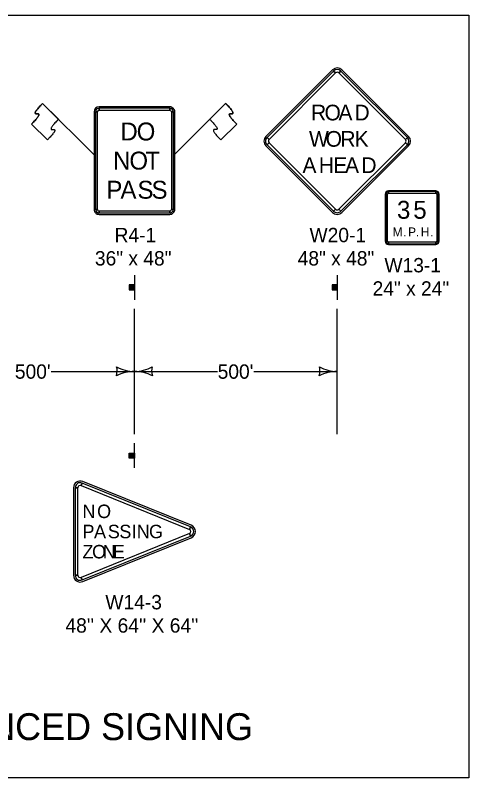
# Model space of a CAD drawing. Extents: x -2134934 to -2119606, y -2139046 to -2137036.
# Drawn here: x -2120111 to -2119606, y -2137987 to -2137136 of the extents above; entities that cross this region are included whole.
import ezdxf

# ---------------------------------------------------------------- set-up
doc = ezdxf.new("R2010")
doc.units = 0
for name, color, linetype in [('dsnStdLabel', 7, 'Continuous'), ('Level 2', 7, 'Continuous'), ('Level 5', 7, 'Continuous')]:
    doc.layers.add(name, color=color, linetype=linetype)

msp = doc.modelspace()

# ---------------------------------------------------------------- linework, layer by layer
at = {"layer": 'dsnStdLabel'}
for p, q in [((-2119757.65, -2137196.82), (-2119831.9, -2137271.07)), ((-2119756.32, -2137198.15), (-2119754.11, -2137200.36)), ((-2119750.58, -2137200.36), (-2119748.37, -2137198.15)), ((-2119672.8, -2137271.07), (-2119747.04, -2137196.82)), ((-2120023.38, -2137291.63), (-2120080.72, -2137234.33)), ((-2120080.72, -2137234.33), (-2120063.03, -2137252.01)), ((-2119934.09, -2137291.63), (-2119876.77, -2137234.32)), ((-2119876.77, -2137234.32), (-2119894.45, -2137252)), ((-2120023.38, -2137243.74), (-2120023.38, -2137352.49)), ((-2120021.82, -2137243.74), (-2120019.63, -2137243.74)), ((-2119939.01, -2137238.12), (-2120017.76, -2137238.12)), ((-2120017.76, -2137241.87), (-2120017.76, -2137239.68)), ((-2119939.01, -2137239.68), (-2119939.01, -2137241.87)), ((-2119937.13, -2137243.74), (-2119934.94, -2137243.74)), ((-2119933.38, -2137352.49), (-2119933.38, -2137243.74)), ((-2120075.41, -2137275), (-2120093.09, -2137257.33)), ((-2119882.07, -2137274.99), (-2119864.39, -2137257.31)), ((-2119828.36, -2137274.6), (-2119830.57, -2137272.39)), ((-2119830.57, -2137280.35), (-2119828.36, -2137278.14)), ((-2119674.12, -2137272.39), (-2119676.33, -2137274.6)), ((-2119676.33, -2137278.14), (-2119674.12, -2137280.35)), ((-2119831.9, -2137281.67), (-2119757.65, -2137355.92)), ((-2119747.04, -2137355.92), (-2119672.8, -2137281.67)), ((-2119698.83, -2137335.51), (-2119698.83, -2137388.01)), ((-2119697.89, -2137335.51), (-2119696.33, -2137335.51)), ((-2119642.58, -2137331.76), (-2119695.08, -2137331.76)), ((-2119695.08, -2137334.26), (-2119695.08, -2137332.7)), ((-2119642.58, -2137332.7), (-2119642.58, -2137334.26)), ((-2119641.33, -2137335.51), (-2119639.76, -2137335.51)), ((-2119638.83, -2137388.01), (-2119638.83, -2137335.51)), ((-2120019.63, -2137352.49), (-2120021.82, -2137352.49)), ((-2120017.76, -2137356.55), (-2120017.76, -2137354.37)), ((-2119939.01, -2137354.37), (-2119939.01, -2137356.55)), ((-2119934.94, -2137352.49), (-2119937.13, -2137352.49)), ((-2119754.11, -2137352.38), (-2119756.32, -2137354.59)), ((-2119748.37, -2137354.59), (-2119750.58, -2137352.38)), ((-2120017.76, -2137358.12), (-2119939.01, -2137358.12)), ((-2119696.33, -2137388.01), (-2119697.89, -2137388.01)), ((-2119639.76, -2137388.01), (-2119641.33, -2137388.01)), ((-2119695.08, -2137390.82), (-2119695.08, -2137389.26)), ((-2119695.08, -2137391.76), (-2119642.58, -2137391.76)), ((-2119642.58, -2137389.26), (-2119642.58, -2137390.82)), ((-2120037.86, -2137660.69), (-2120036.68, -2137657.79)), ((-2119915.16, -2137704.93), (-2120035.98, -2137656.05)), ((-2120046.29, -2137663.01), (-2120046.29, -2137760.76)), ((-2120044.42, -2137663.01), (-2120041.29, -2137663.01)), ((-2119915.86, -2137706.67), (-2119917.03, -2137709.57)), ((-2120035.98, -2137767.71), (-2119915.16, -2137718.84)), ((-2119917.03, -2137714.2), (-2119915.86, -2137717.1)), ((-2120041.29, -2137760.76), (-2120044.42, -2137760.76)), ((-2120036.68, -2137765.97), (-2120037.86, -2137763.08))]:
    msp.add_line(p, q, dxfattribs=at)
for points in [[(-2120726.97, -2137135.95), (-2119605.73, -2137135.95), (-2119605.73, -2137986.59), (-2120726.97, -2137986.59)], [(-2119756.32, -2137198.15), (-2119830.57, -2137272.39), (-2119828.36, -2137274.6), (-2119754.11, -2137200.36), (-2119756.32, -2137198.15)], [(-2119674.12, -2137272.39), (-2119748.37, -2137198.15), (-2119750.58, -2137200.36), (-2119676.33, -2137274.6), (-2119674.12, -2137272.39)], [(-2120021.82, -2137243.74), (-2120021.82, -2137352.49), (-2120019.63, -2137352.49), (-2120019.63, -2137243.74), (-2120021.82, -2137243.74)], [(-2119939.01, -2137239.68), (-2120017.76, -2137239.68), (-2120017.76, -2137241.87), (-2119939.01, -2137241.87), (-2119939.01, -2137239.68)], [(-2119934.94, -2137352.49), (-2119934.94, -2137243.74), (-2119937.13, -2137243.74), (-2119937.13, -2137352.49), (-2119934.94, -2137352.49)], [(-2119830.57, -2137280.35), (-2119756.32, -2137354.59), (-2119754.11, -2137352.38), (-2119828.36, -2137278.14), (-2119830.57, -2137280.35)], [(-2119748.37, -2137354.59), (-2119674.12, -2137280.35), (-2119676.33, -2137278.14), (-2119750.58, -2137352.38), (-2119748.37, -2137354.59)], [(-2119697.89, -2137335.51), (-2119697.89, -2137388.01), (-2119696.33, -2137388.01), (-2119696.33, -2137335.51), (-2119697.89, -2137335.51)], [(-2119642.58, -2137332.7), (-2119695.08, -2137332.7), (-2119695.08, -2137334.26), (-2119642.58, -2137334.26), (-2119642.58, -2137332.7)], [(-2119639.76, -2137388.01), (-2119639.76, -2137335.51), (-2119641.33, -2137335.51), (-2119641.33, -2137388.01), (-2119639.76, -2137388.01)], [(-2120017.76, -2137356.55), (-2119939.01, -2137356.55), (-2119939.01, -2137354.37), (-2120017.76, -2137354.37), (-2120017.76, -2137356.55)], [(-2119695.08, -2137390.82), (-2119642.58, -2137390.82), (-2119642.58, -2137389.26), (-2119695.08, -2137389.26), (-2119695.08, -2137390.82)], [(-2119915.86, -2137706.67), (-2120036.68, -2137657.79), (-2120037.86, -2137660.69), (-2119917.03, -2137709.57), (-2119915.86, -2137706.67)], [(-2120044.42, -2137663.01), (-2120044.42, -2137760.76), (-2120041.29, -2137760.76), (-2120041.29, -2137663.01), (-2120044.42, -2137663.01)], [(-2120036.68, -2137765.97), (-2119915.86, -2137717.1), (-2119917.03, -2137714.2), (-2120037.86, -2137763.08), (-2120036.68, -2137765.97)]]:
    msp.add_lwpolyline(points, close=True, dxfattribs=at)
for centre, radius, start, end in [((-2119752.35, -2137202.12), 7.5, 44.99999, 134.99974), ((-2119752.35, -2137202.12), 5.62, 44.99999, 134.99974), ((-2119752.35, -2137202.12), 2.5, 44.99999, 134.99974), ((-2120017.76, -2137243.74), 5.62, 90.00021, 179.99985), ((-2120017.76, -2137243.74), 4.06, 90.00021, 179.99985), ((-2120017.76, -2137243.74), 1.87, 90.00021, 179.99985), ((-2119939.01, -2137243.74), 5.62, 0, 90.00021), ((-2119939.01, -2137243.74), 4.06, 0, 90.00021), ((-2119939.01, -2137243.74), 1.87, 0, 90.00021), ((-2119826.59, -2137276.37), 7.5, 134.99974, 224.99995), ((-2119826.59, -2137276.37), 5.62, 134.99974, 224.99995), ((-2119826.59, -2137276.37), 2.5, 134.99974, 224.99995), ((-2119678.1, -2137276.37), 2.5, 315.00016, 44.9998), ((-2119678.1, -2137276.37), 5.62, 315.00016, 44.9998), ((-2119678.1, -2137276.37), 7.5, 315.00016, 44.9998), ((-2119695.08, -2137335.51), 3.75, 90.00021, 179.99985), ((-2119695.08, -2137335.51), 2.81, 90.00021, 179.99985), ((-2119695.08, -2137335.51), 1.25, 90.00021, 179.99985), ((-2119642.58, -2137335.51), 3.75, 0, 90.00021), ((-2119642.58, -2137335.51), 2.81, 0, 90.00021), ((-2119642.58, -2137335.51), 1.25, 0, 90.00021), ((-2120017.76, -2137352.49), 5.62, 179.99985, 270.00006), ((-2120017.76, -2137352.49), 4.06, 179.99985, 270.00006), ((-2120017.76, -2137352.49), 1.87, 179.99985, 270.00006), ((-2119939.01, -2137352.49), 5.62, 270.00006, 0.00027), ((-2119939.01, -2137352.49), 4.06, 270.00006, 0.00027), ((-2119939.01, -2137352.49), 1.87, 270.00006, 0.00027), ((-2119752.35, -2137350.62), 5.62, 224.99995, 315.00016), ((-2119752.35, -2137350.62), 2.5, 224.99995, 315.00016), ((-2119752.35, -2137350.62), 7.5, 224.99995, 315.00016), ((-2119695.08, -2137388.01), 3.75, 179.99985, 270.00006), ((-2119695.08, -2137388.01), 2.81, 179.99985, 270.00006), ((-2119695.08, -2137388.01), 1.25, 179.99985, 270.00006), ((-2119642.58, -2137388.01), 3.75, 270.00006, 0.00027), ((-2119642.58, -2137388.01), 2.81, 270.00006, 0.00027), ((-2119642.58, -2137388.01), 1.25, 270.00006, 0.00027), ((-2120038.79, -2137663.01), 7.5, 67.97571, 179.99985), ((-2120038.79, -2137663.01), 5.62, 67.97571, 179.99985), ((-2120038.79, -2137663.01), 2.5, 67.97571, 179.99985), ((-2119917.97, -2137711.88), 2.5, 292.02456, 67.97541), ((-2119917.97, -2137711.88), 5.62, 292.02456, 67.97541), ((-2119917.97, -2137711.88), 7.5, 292.02456, 67.97598), ((-2120038.79, -2137760.76), 7.5, 179.99985, 292.02456), ((-2120038.79, -2137760.76), 5.62, 179.99985, 292.02456), ((-2120038.79, -2137760.76), 2.5, 179.99985, 292.02456)]:
    msp.add_arc(centre, radius, start, end, dxfattribs=at)
for points in [[(-2120093.09, -2137257.33), (-2120080.71, -2137244.95), (-2120093.09, -2137246.72), (-2120080.72, -2137234.33)], [(-2119864.39, -2137257.31), (-2119876.77, -2137244.93), (-2119864.39, -2137246.7), (-2119876.77, -2137234.32)], [(-2120063.03, -2137252.01), (-2120075.4, -2137264.4), (-2120063.03, -2137262.62), (-2120075.41, -2137275)], [(-2119894.45, -2137252), (-2119882.07, -2137264.38), (-2119894.44, -2137262.61), (-2119882.07, -2137274.99)]]:
    msp.add_open_spline(points, degree=2, dxfattribs=at)
at = {"layer": 'Level 2'}
for p, q in [((-2119978.38, -2137425.94), (-2119978.38, -2137453.44)), ((-2119752.35, -2137425.94), (-2119752.35, -2137453.44)), ((-2119983.71, -2137436.8), (-2119983.71, -2137442.39)), ((-2119983.39, -2137442.39), (-2119983.39, -2137436.8)), ((-2119983.16, -2137436.8), (-2119983.16, -2137442.39)), ((-2119982.85, -2137442.39), (-2119982.85, -2137436.8)), ((-2119982.62, -2137436.8), (-2119982.64, -2137442.39)), ((-2119982.21, -2137442.39), (-2119982.19, -2137436.8)), ((-2119981.98, -2137436.8), (-2119981.98, -2137442.39)), ((-2119981.55, -2137442.39), (-2119981.55, -2137436.8)), ((-2119981.18, -2137436.8), (-2119981.18, -2137442.39)), ((-2119980.86, -2137442.39), (-2119980.84, -2137436.8)), ((-2119980.63, -2137436.8), (-2119980.63, -2137442.39)), ((-2119980.37, -2137442.39), (-2119980.37, -2137436.8)), ((-2119980.03, -2137436.8), (-2119980.03, -2137442.39)), ((-2119979.83, -2137442.39), (-2119979.83, -2137436.8)), ((-2119979.6, -2137436.8), (-2119979.6, -2137442.39)), ((-2119979.34, -2137442.39), (-2119979.34, -2137436.8)), ((-2119979.08, -2137436.8), (-2119979.08, -2137442.39)), ((-2119978.79, -2137442.39), (-2119978.79, -2137436.8)), ((-2119757.67, -2137436.8), (-2119757.67, -2137442.39)), ((-2119757.35, -2137442.39), (-2119757.35, -2137436.8)), ((-2119757.13, -2137436.8), (-2119757.13, -2137442.39)), ((-2119756.81, -2137442.39), (-2119756.81, -2137436.8)), ((-2119756.58, -2137436.8), (-2119756.6, -2137442.39)), ((-2119756.17, -2137442.39), (-2119756.15, -2137436.8)), ((-2119755.95, -2137436.8), (-2119755.95, -2137442.39)), ((-2119755.52, -2137442.39), (-2119755.52, -2137436.8)), ((-2119755.14, -2137436.8), (-2119755.14, -2137442.39)), ((-2119754.82, -2137442.39), (-2119754.8, -2137436.8)), ((-2119754.6, -2137436.8), (-2119754.6, -2137442.39)), ((-2119754.33, -2137442.39), (-2119754.33, -2137436.8)), ((-2119754, -2137436.8), (-2119754, -2137442.39)), ((-2119753.79, -2137442.39), (-2119753.79, -2137436.8)), ((-2119753.57, -2137436.8), (-2119753.57, -2137442.39)), ((-2119753.3, -2137442.39), (-2119753.3, -2137436.8)), ((-2119753.04, -2137436.8), (-2119753.04, -2137442.39)), ((-2119752.76, -2137442.39), (-2119752.76, -2137436.8)), ((-2119978.38, -2137603.44), (-2119978.38, -2137463.44)), ((-2119752.35, -2137603.44), (-2119752.35, -2137463.44)), ((-2120071.15, -2137533.44), (-2119978.38, -2137533.44)), ((-2119978.38, -2137533.44), (-2119885.61, -2137533.44)), ((-2119845.11, -2137533.44), (-2119752.35, -2137533.44)), ((-2119978.38, -2137640.94), (-2119978.38, -2137613.44)), ((-2119983.71, -2137630.08), (-2119983.71, -2137624.49)), ((-2119983.39, -2137624.49), (-2119983.39, -2137630.08)), ((-2119983.16, -2137630.08), (-2119983.16, -2137624.49)), ((-2119982.85, -2137624.49), (-2119982.85, -2137630.08)), ((-2119982.62, -2137630.08), (-2119982.64, -2137624.49)), ((-2119982.21, -2137624.49), (-2119982.19, -2137630.08)), ((-2119981.98, -2137630.08), (-2119981.98, -2137624.49)), ((-2119981.55, -2137624.49), (-2119981.55, -2137630.08)), ((-2119981.18, -2137630.08), (-2119981.18, -2137624.49)), ((-2119980.86, -2137624.49), (-2119980.84, -2137630.08)), ((-2119980.63, -2137630.08), (-2119980.63, -2137624.49)), ((-2119980.37, -2137624.49), (-2119980.37, -2137630.08)), ((-2119980.03, -2137630.08), (-2119980.03, -2137624.49)), ((-2119979.83, -2137624.49), (-2119979.83, -2137630.08)), ((-2119979.6, -2137630.08), (-2119979.6, -2137624.49)), ((-2119979.34, -2137624.49), (-2119979.34, -2137630.08)), ((-2119979.08, -2137630.08), (-2119979.08, -2137624.49)), ((-2119978.79, -2137624.49), (-2119978.79, -2137630.08))]:
    msp.add_line(p, q, dxfattribs=at)
for points in [[(-2119978.48, -2137442.39), (-2119978.48, -2137436.76), (-2119984.1, -2137436.76), (-2119984.1, -2137442.39)], [(-2119752.44, -2137442.39), (-2119752.44, -2137436.76), (-2119758.07, -2137436.76), (-2119758.07, -2137442.39)], [(-2119978.48, -2137624.49), (-2119978.48, -2137630.12), (-2119984.1, -2137630.12), (-2119984.1, -2137624.49)]]:
    msp.add_lwpolyline(points, close=True, dxfattribs=at)
for centre, radius, start, end in [((-2120014, -2137532.82), 16.42, 341.26665, 16.73335), ((-2119979.11, -2137575.93), 42.5, 89.0176, 117.07249), ((-2119977.63, -2137490.95), 42.5, 240.92751, 268.9824), ((-2119979.14, -2137490.95), 42.5, 271.0176, 299.07249), ((-2119977.65, -2137575.93), 42.5, 62.92751, 90.9824), ((-2119942.76, -2137532.82), 16.42, 163.26665, 198.73335), ((-2119787.96, -2137532.82), 16.42, 341.26665, 16.73335), ((-2119753.07, -2137575.93), 42.5, 89.0176, 117.07249), ((-2119751.59, -2137490.95), 42.5, 240.92751, 268.9824)]:
    msp.add_arc(centre, radius, start, end, dxfattribs=at)
at = {"layer": 'Level 5'}
for p, q in [((-2120093.09, -2137257.33), (-2120075.41, -2137275)), ((-2119864.39, -2137257.31), (-2119882.07, -2137274.99))]:
    msp.add_line(p, q, dxfattribs=at)
for points in [[(-2120080.72, -2137234.33), (-2120093.09, -2137246.72), (-2120080.71, -2137244.95), (-2120093.09, -2137257.33)], [(-2119876.77, -2137234.32), (-2119864.39, -2137246.7), (-2119876.77, -2137244.93), (-2119864.39, -2137257.31)], [(-2120063.03, -2137252.01), (-2120075.4, -2137264.4), (-2120063.03, -2137262.62), (-2120075.41, -2137275)], [(-2119894.45, -2137252), (-2119882.07, -2137264.38), (-2119894.44, -2137262.61), (-2119882.07, -2137274.99)]]:
    msp.add_open_spline(points, degree=2, dxfattribs=at)

# ---------------------------------------------------------------- texts
at = {"layer": 'dsnStdLabel'}
for s, height, p in [('R', 17.5, (-2119781.51, -2137253.25)), ('O', 17.5, (-2119766.5, -2137253.25)), ('A', 17.5, (-2119750.95, -2137253.25)), ('D', 17.5, (-2119733.07, -2137253.25)), ('D', 20, (-2119994.01, -2137275.62)), ('O', 20, (-2119975.88, -2137275.62)), ('W', 17.5, (-2119783.79, -2137282.62)), ('O', 17.5, (-2119765.2, -2137282.62)), ('R', 17.5, (-2119748.79, -2137282.62)), ('K', 17.5, (-2119732.93, -2137282.62)), ('N', 20, (-2120002.13, -2137308.12)), ('O', 20, (-2119984.01, -2137308.12)), ('T', 20, (-2119966.19, -2137308.12)), ('A', 17.5, (-2119791.07, -2137312)), ('H', 17.5, (-2119772.86, -2137312)), ('E', 17.5, (-2119756.63, -2137312)), ('A', 17.5, (-2119743.59, -2137312)), ('D', 17.5, (-2119725.38, -2137312)), ('P', 20, (-2120009.65, -2137340.62)), ('A', 20, (-2119993.96, -2137340.62)), ('S', 20, (-2119974.99, -2137340.62)), ('S', 20, (-2119959.3, -2137340.62)), ('3', 20, (-2119685.68, -2137363)), ('5', 20, (-2119667.55, -2137363)), ('R4-1', 16, (-2120000.55, -2137389.12)), ('W20-1', 16, (-2119783.2, -2137389.12)), ('M', 10, (-2119690.6, -2137382.7)), ('P', 10, (-2119673.35, -2137382.7)), ('H', 10, (-2119659.23, -2137382.7)), ('.', 10, (-2119678.81, -2137382.7)), ('.', 10, (-2119664.69, -2137382.7)), ('.', 10, (-2119648.76, -2137382.7)), ('36" x 48"', 16, (-2120022.45, -2137415.12)), ('48" x 48"', 16, (-2119796.41, -2137415.12)), ('W13-1', 16, (-2119699.68, -2137422.76)), ('24" x 24"', 16, (-2119712.89, -2137448.76)), ('N', 15, (-2120036.32, -2137696.88)), ('O', 15, (-2120019.99, -2137696.88)), ('P', 15, (-2120036.32, -2137719.38)), ('A', 15, (-2120023.43, -2137719.38)), ('S', 15, (-2120008.08, -2137719.38)), ('S', 15, (-2119995.19, -2137719.38)), ('I', 15, (-2119981.6, -2137719.38)), ('N', 15, (-2119975.74, -2137719.38)), ('G', 15, (-2119962.14, -2137719.38)), ('Z', 15, (-2120036.32, -2137741.88)), ('O', 15, (-2120025.59, -2137741.88)), ('N', 15, (-2120013.76, -2137741.88)), ('E', 15, (-2120002.4, -2137741.88)), ('W14-3', 16, (-2120010.78, -2137798.71)), ("48'' X 64'' X 64''", 16, (-2120055.27, -2137824.71)), ('265TH ROAD ADVANCED SIGNING', 30, (-2120508.22, -2137944.59))]:
    msp.add_text(s, height=height, dxfattribs=at).set_placement(p)
at = {"layer": 'Level 2'}
for p in [(-2120111.65, -2137541.44), (-2119885.61, -2137541.44)]:
    msp.add_text("500'", height=16, dxfattribs=at).set_placement(p)

doc.saveas('drawing.dxf')
